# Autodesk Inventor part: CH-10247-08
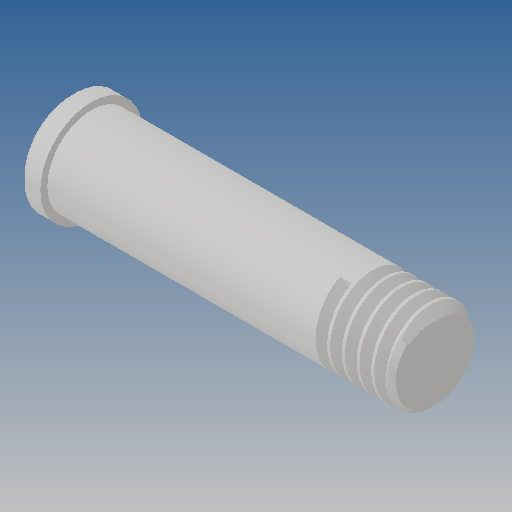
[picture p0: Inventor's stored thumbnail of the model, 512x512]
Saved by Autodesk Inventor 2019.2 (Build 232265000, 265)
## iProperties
Created: 2012-09
Part Number: CH-10247-08
Material: Ogólny
Document SubType Name: Modeling
Designer: CADENGINEERING4
Density: 1 g/cm^3
Appearance: Domyślna
Author: CADENGINEERING4
Revision Number: ÈÎºÎ
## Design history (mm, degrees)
feature "ÇÐ³ý-É¨Ãè2"
node "Bryła1"
